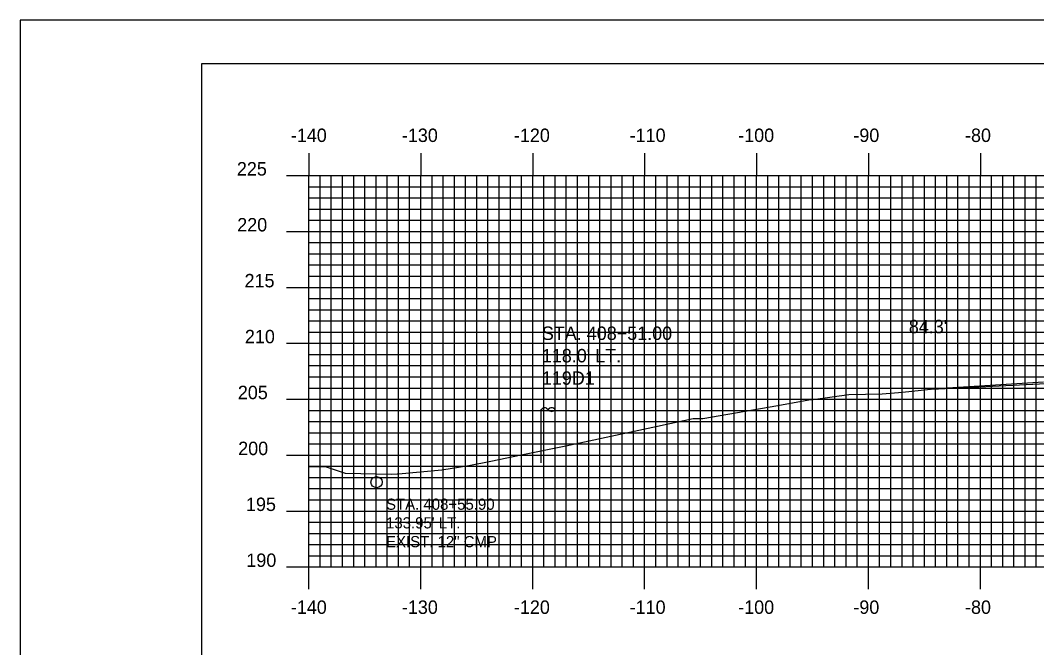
# Model space of a CAD drawing. Extents: x 852529 to 852872, y 364785 to 365005.
# Drawn here: x 852528.9 to 852619.8, y 364949 to 365005.1 of the extents above; entities that cross this region are included whole.
import ezdxf

# ---------------------------------------------------------------- set-up
doc = ezdxf.new("R2010")
doc.units = 0
for name, color, linetype in [('ANNOTATION', 7, 'Continuous'), ('BORDER', 7, 'Continuous'), ('D_Drainage_Culvert', 7, 'Continuous'), ('D_Drainage_Text', 7, 'Continuous'), ('D_Text_Monospaced', 7, 'Continuous'), ('D_Text_Standard', 7, 'Continuous'), ('D_Utilities_Pole_Joint', 7, 'Continuous'), ('H_V ANNOTATION', 7, 'Continuous'), ('MAJOR', 7, 'Continuous'), ('MINOR', 7, 'Continuous'), ('PLOT BOUNDARY', 7, 'Continuous'), ('S_Roadway_Centerline', 7, 'Continuous')]:
    doc.layers.add(name, color=color, linetype=linetype)

msp = doc.modelspace()

# ---------------------------------------------------------------- linework, layer by layer
at = {"layer": 'ANNOTATION'}
msp.add_lwpolyline([(852610.409, 364972.142), (852621.838, 364972.694), (852637.933, 364974.11)], dxfattribs=at)
at = {"layer": 'BORDER'}
msp.add_lwpolyline([(852545.131, 364791.233), (852865.131, 364791.233), (852865.131, 365001.233), (852545.131, 365001.233)], close=True, dxfattribs=at)
at = {"layer": 'D_Drainage_Culvert'}
msp.add_circle((852560.778, 364963.812), 0.5, dxfattribs=at)
at = {"layer": 'D_Utilities_Pole_Joint'}
for p, q in [((852575.481, 364970.306), (852575.637, 364970.417)), ((852575.949, 364970.417), (852576.105, 364970.306)), ((852576.262, 364970.417), (852576.105, 364970.306)), ((852576.731, 364970.306), (852576.575, 364970.417)), ((852575.481, 364965.549), (852575.481, 364970.306)), ((852576.105, 364970.306), (852576.262, 364970.196)), ((852576.575, 364970.196), (852576.731, 364970.306)), ((852576.731, 364965.549), (852576.731, 364970.306))]:
    msp.add_line(p, q, dxfattribs=at)
for centre, start, end in [((852575.793, 364970.196), 90, 125.26439), ((852575.793, 364970.196), 54.73561, 90), ((852576.418, 364970.196), 90, 125.26439), ((852576.418, 364970.196), 54.73561, 90), ((852576.418, 364970.417), 234.73561, 270), ((852576.418, 364970.417), 270, 305.26439)]:
    msp.add_arc(centre, 0.271, start, end, dxfattribs=at)
at = {"layer": 'MAJOR'}
for p, q in [((852554.731, 364993.237), (852554.731, 364991.233)), ((852564.731, 364993.237), (852564.731, 364991.233)), ((852574.731, 364993.237), (852574.731, 364991.233)), ((852584.731, 364993.237), (852584.731, 364991.233)), ((852594.731, 364993.237), (852594.731, 364991.233)), ((852604.731, 364993.237), (852604.731, 364991.233)), ((852614.731, 364993.237), (852614.731, 364991.233)), ((852552.727, 364991.233), (852554.731, 364991.233)), ((852554.731, 364991.233), (852834.731, 364991.233)), ((852554.731, 364956.233), (852554.731, 364991.233)), ((852554.731, 364956.233), (852554.731, 364991.233)), ((852554.731, 364991.233), (852834.731, 364991.233)), ((852564.731, 364956.233), (852564.731, 364991.233)), ((852574.731, 364956.233), (852574.731, 364991.233)), ((852584.731, 364956.233), (852584.731, 364991.233)), ((852594.731, 364956.233), (852594.731, 364991.233)), ((852604.731, 364956.233), (852604.731, 364991.233)), ((852614.731, 364956.233), (852614.731, 364991.233)), ((852552.727, 364986.233), (852554.731, 364986.233)), ((852554.731, 364986.233), (852834.731, 364986.233)), ((852552.727, 364981.233), (852554.731, 364981.233)), ((852554.731, 364981.233), (852834.731, 364981.233)), ((852552.727, 364976.233), (852554.731, 364976.233)), ((852554.731, 364976.233), (852834.731, 364976.233)), ((852552.727, 364971.233), (852554.731, 364971.233)), ((852554.731, 364971.233), (852834.731, 364971.233)), ((852552.727, 364966.233), (852554.731, 364966.233)), ((852554.731, 364966.233), (852834.731, 364966.233)), ((852552.727, 364961.233), (852554.731, 364961.233)), ((852554.731, 364961.233), (852834.731, 364961.233)), ((852552.727, 364956.233), (852554.731, 364956.233)), ((852554.731, 364956.233), (852834.731, 364956.233)), ((852554.731, 364956.233), (852834.731, 364956.233)), ((852554.731, 364954.229), (852554.731, 364956.233)), ((852564.731, 364954.229), (852564.731, 364956.233)), ((852574.731, 364954.229), (852574.731, 364956.233)), ((852584.731, 364954.229), (852584.731, 364956.233)), ((852594.731, 364954.229), (852594.731, 364956.233)), ((852604.731, 364954.229), (852604.731, 364956.233)), ((852614.731, 364954.229), (852614.731, 364956.233))]:
    msp.add_line(p, q, dxfattribs=at)
at = {"layer": 'MINOR'}
for p, q in [((852555.731, 364956.233), (852555.731, 364991.233)), ((852556.731, 364956.233), (852556.731, 364991.233)), ((852557.731, 364956.233), (852557.731, 364991.233)), ((852558.731, 364956.233), (852558.731, 364991.233)), ((852559.731, 364956.233), (852559.731, 364991.233)), ((852560.731, 364956.233), (852560.731, 364991.233)), ((852561.731, 364956.233), (852561.731, 364991.233)), ((852562.731, 364956.233), (852562.731, 364991.233)), ((852563.731, 364956.233), (852563.731, 364991.233)), ((852565.731, 364956.233), (852565.731, 364991.233)), ((852566.731, 364956.233), (852566.731, 364991.233)), ((852567.731, 364956.233), (852567.731, 364991.233)), ((852568.731, 364956.233), (852568.731, 364991.233)), ((852569.731, 364956.233), (852569.731, 364991.233)), ((852570.731, 364956.233), (852570.731, 364991.233)), ((852571.731, 364956.233), (852571.731, 364991.233)), ((852572.731, 364956.233), (852572.731, 364991.233)), ((852573.731, 364956.233), (852573.731, 364991.233)), ((852575.731, 364956.233), (852575.731, 364991.233)), ((852576.731, 364956.233), (852576.731, 364991.233)), ((852577.731, 364956.233), (852577.731, 364991.233)), ((852578.731, 364956.233), (852578.731, 364991.233)), ((852579.731, 364956.233), (852579.731, 364991.233)), ((852580.731, 364956.233), (852580.731, 364991.233)), ((852581.731, 364956.233), (852581.731, 364991.233)), ((852582.731, 364956.233), (852582.731, 364991.233)), ((852583.731, 364956.233), (852583.731, 364991.233)), ((852585.731, 364956.233), (852585.731, 364991.233)), ((852586.731, 364956.233), (852586.731, 364991.233)), ((852587.731, 364956.233), (852587.731, 364991.233)), ((852588.731, 364956.233), (852588.731, 364991.233)), ((852589.731, 364956.233), (852589.731, 364991.233)), ((852590.731, 364956.233), (852590.731, 364991.233)), ((852591.731, 364956.233), (852591.731, 364991.233)), ((852592.731, 364956.233), (852592.731, 364991.233)), ((852593.731, 364956.233), (852593.731, 364991.233)), ((852595.731, 364956.233), (852595.731, 364991.233)), ((852596.731, 364956.233), (852596.731, 364991.233)), ((852597.731, 364956.233), (852597.731, 364991.233)), ((852598.731, 364956.233), (852598.731, 364991.233)), ((852599.731, 364956.233), (852599.731, 364991.233)), ((852600.731, 364956.233), (852600.731, 364991.233)), ((852601.731, 364956.233), (852601.731, 364991.233)), ((852602.731, 364956.233), (852602.731, 364991.233)), ((852603.731, 364956.233), (852603.731, 364991.233)), ((852605.731, 364956.233), (852605.731, 364991.233)), ((852606.731, 364956.233), (852606.731, 364991.233)), ((852607.731, 364956.233), (852607.731, 364991.233)), ((852608.731, 364956.233), (852608.731, 364991.233)), ((852609.731, 364956.233), (852609.731, 364991.233)), ((852610.731, 364956.233), (852610.731, 364991.233)), ((852611.731, 364956.233), (852611.731, 364991.233)), ((852612.731, 364956.233), (852612.731, 364991.233)), ((852613.731, 364956.233), (852613.731, 364991.233)), ((852615.731, 364956.233), (852615.731, 364991.233)), ((852616.731, 364956.233), (852616.731, 364991.233)), ((852617.731, 364956.233), (852617.731, 364991.233)), ((852618.731, 364956.233), (852618.731, 364991.233)), ((852619.731, 364956.233), (852619.731, 364991.233)), ((852554.731, 364990.233), (852834.731, 364990.233)), ((852554.731, 364990.233), (852556.735, 364990.233)), ((852554.731, 364989.233), (852834.731, 364989.233)), ((852554.731, 364989.233), (852556.735, 364989.233)), ((852554.731, 364988.233), (852834.731, 364988.233)), ((852554.731, 364988.233), (852556.735, 364988.233)), ((852554.731, 364987.233), (852834.731, 364987.233)), ((852554.731, 364987.233), (852556.735, 364987.233)), ((852554.731, 364985.233), (852834.731, 364985.233)), ((852554.731, 364985.233), (852556.735, 364985.233)), ((852554.731, 364984.233), (852834.731, 364984.233)), ((852554.731, 364984.233), (852556.735, 364984.233)), ((852554.731, 364983.233), (852834.731, 364983.233)), ((852554.731, 364983.233), (852556.735, 364983.233)), ((852554.731, 364982.233), (852834.731, 364982.233)), ((852554.731, 364982.233), (852556.735, 364982.233)), ((852554.731, 364980.233), (852834.731, 364980.233)), ((852554.731, 364980.233), (852556.735, 364980.233)), ((852554.731, 364979.233), (852834.731, 364979.233)), ((852554.731, 364979.233), (852556.735, 364979.233)), ((852554.731, 364978.233), (852834.731, 364978.233)), ((852554.731, 364978.233), (852556.735, 364978.233)), ((852554.731, 364977.233), (852834.731, 364977.233)), ((852554.731, 364977.233), (852556.735, 364977.233)), ((852554.731, 364975.233), (852834.731, 364975.233)), ((852554.731, 364975.233), (852556.735, 364975.233)), ((852554.731, 364974.233), (852834.731, 364974.233)), ((852554.731, 364974.233), (852556.735, 364974.233)), ((852554.731, 364973.233), (852834.731, 364973.233)), ((852554.731, 364973.233), (852556.735, 364973.233)), ((852554.731, 364972.233), (852834.731, 364972.233)), ((852554.731, 364972.233), (852556.735, 364972.233)), ((852554.731, 364970.233), (852834.731, 364970.233)), ((852554.731, 364970.233), (852556.735, 364970.233)), ((852554.731, 364969.233), (852834.731, 364969.233)), ((852554.731, 364969.233), (852556.735, 364969.233)), ((852554.731, 364968.233), (852834.731, 364968.233)), ((852554.731, 364968.233), (852556.735, 364968.233)), ((852554.731, 364967.233), (852834.731, 364967.233)), ((852554.731, 364967.233), (852556.735, 364967.233)), ((852554.731, 364965.233), (852834.731, 364965.233)), ((852554.731, 364965.233), (852556.735, 364965.233)), ((852554.731, 364964.233), (852834.731, 364964.233)), ((852554.731, 364964.233), (852556.735, 364964.233)), ((852554.731, 364963.233), (852834.731, 364963.233)), ((852554.731, 364963.233), (852556.735, 364963.233)), ((852554.731, 364962.233), (852834.731, 364962.233)), ((852554.731, 364962.233), (852556.735, 364962.233)), ((852554.731, 364960.233), (852834.731, 364960.233)), ((852554.731, 364960.233), (852556.735, 364960.233)), ((852554.731, 364959.233), (852834.731, 364959.233)), ((852554.731, 364959.233), (852556.735, 364959.233)), ((852554.731, 364958.233), (852834.731, 364958.233)), ((852554.731, 364958.233), (852556.735, 364958.233)), ((852554.731, 364957.233), (852834.731, 364957.233)), ((852554.731, 364957.233), (852556.735, 364957.233))]:
    msp.add_line(p, q, dxfattribs=at)
at = {"layer": 'PLOT BOUNDARY'}
msp.add_lwpolyline([(852528.944, 364785.114), (852868.944, 364785.114), (852868.944, 365005.114), (852528.944, 365005.114)], close=True, dxfattribs=at)
at = {"layer": 'S_Roadway_Centerline'}
msp.add_lwpolyline([(852554.731, 364965.206), (852556.286, 364965.195), (852557.97, 364964.612), (852562.135, 364964.523), (852562.605, 364964.56), (852562.736, 364964.572), (852566.596, 364964.909), (852569.025, 364965.297), (852570.997, 364965.696), (852573.686, 364966.253), (852577.693, 364967.066), (852589.072, 364969.51), (852589.93, 364969.495), (852596.624, 364970.667), (852599.418, 364971.175), (852599.778, 364971.211), (852602.964, 364971.651), (852605.954, 364971.722), (852607.773, 364971.847), (852610.84, 364972.19), (852620.362, 364972.79)], dxfattribs=at)

# ---------------------------------------------------------------- texts
at = {"layer": 'D_Drainage_Text'}
for s, p in [('STA. 408+51.00', (852575.547, 364976.529)), ("118.0' LT.", (852575.547, 364974.525)), ('119D1', (852575.547, 364972.521))]:
    msp.add_text(s, height=1.2, dxfattribs=at).set_placement(p)
at = {"layer": 'D_Text_Monospaced'}
for s, p in [('STA. 408+55.90', (852561.623, 364961.343)), ("133.95' LT.", (852561.623, 364959.675)), ('EXIST. 12" CMP', (852561.623, 364957.995))]:
    msp.add_text(s, height=0.99996, dxfattribs=at).set_placement(p)
at = {"layer": 'D_Text_Standard'}
msp.add_text("84.3'", height=1.2, dxfattribs=at).set_placement((852608.338, 364977.129))
at = {"layer": 'H_V ANNOTATION'}
for s, p in [('-140', (852553.115, 364994.233)), ('-130', (852563.04, 364994.233)), ('-120', (852573.05, 364994.233)), ('-110', (852583.393, 364994.233)), ('-100', (852593.093, 364994.233)), ('-90', (852603.382, 364994.233)), ('-80', (852613.361, 364994.233)), ('225', (852548.294, 364991.233)), ('220', (852548.326, 364986.233)), ('215', (852548.98, 364981.233)), ('210', (852549.012, 364976.233)), ('205', (852548.38, 364971.233)), ('200', (852548.412, 364966.233)), ('195', (852549.108, 364961.233)), ('190', (852549.14, 364956.233)), ('-140', (852553.115, 364952.033)), ('-130', (852563.04, 364952.033)), ('-120', (852573.05, 364952.033)), ('-110', (852583.393, 364952.033)), ('-100', (852593.093, 364952.033)), ('-90', (852603.382, 364952.033)), ('-80', (852613.361, 364952.033))]:
    msp.add_text(s, height=1.2, dxfattribs=at).set_placement(p)
at = {"layer": 'MAJOR'}
msp.add_text('-', height=0.012, dxfattribs=at).set_placement((852554.722, 364956.233))

doc.saveas('drawing.dxf')
